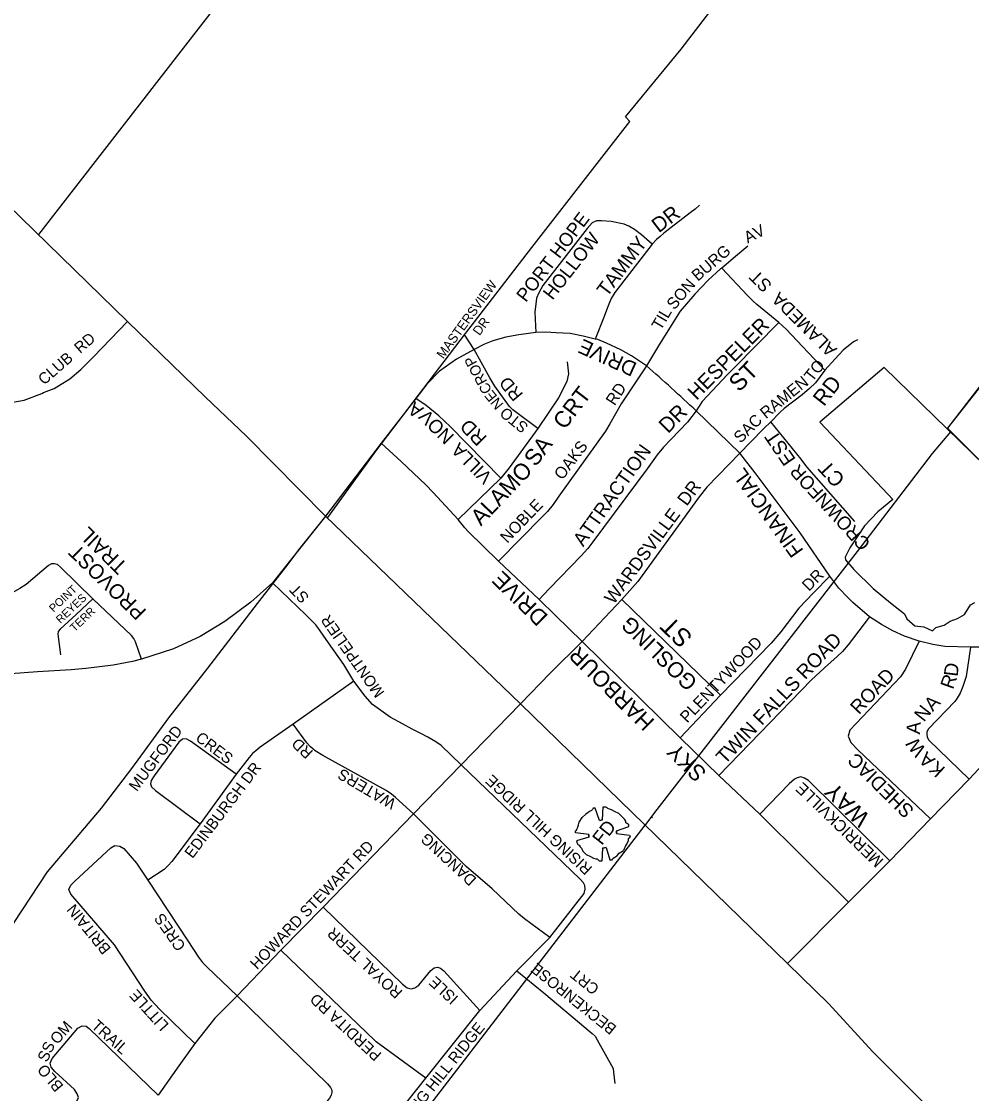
# Model space of a CAD drawing. Extents: x 586326 to 623965, y 4819854 to 4857850.
# Drawn here: x 597455 to 598761, y 4831288 to 4832762 of the extents above; entities that cross this region are included whole.
import ezdxf

# ---------------------------------------------------------------- set-up
doc = ezdxf.new("R2010")
doc.units = 0
for name, color, linetype in [('Fire Syms', 7, 'Continuous'), ('Lots_Concessions', 7, 'Continuous'), ('Major Rds and Hwys', 7, 'Continuous'), ('Minor Rd Lbls', 7, 'Continuous'), ('Minor Rds', 7, 'Continuous'), ('Park Outlines', 7, 'Continuous'), ('Proposed Minor Rds', 7, 'Continuous'), ('Proposed Rd Lbls', 7, 'Continuous'), ('Proposed Secondary Rds', 7, 'Continuous'), ('Secondary Rds Lbls', 7, 'Continuous')]:
    doc.layers.add(name, color=color, linetype=linetype)

msp = doc.modelspace()

# ---------------------------------------------------------------- linework, layer by layer
at = {"layer": 'Fire Syms'}
for points in [[(598254, 4831664.4), (598250, 4831663.4), (598244, 4831680.4), (598241, 4831680.4), (598240, 4831678.4), (598239, 4831677.4), (598237, 4831676.4), (598234, 4831674.4), (598231, 4831672.4), (598226, 4831667.4), (598226, 4831667.4)], [(598250, 4831663.4), (598254, 4831664.4), (598255, 4831682.4), (598258, 4831682.4), (598260, 4831681.4), (598261, 4831680.4), (598263, 4831679.4), (598266, 4831678.4), (598270, 4831676.4), (598276, 4831673.4), (598276, 4831673.4)], [(598273, 4831645.4), (598273, 4831649.4), (598290, 4831655.4), (598290, 4831657.4), (598288, 4831659.4), (598286, 4831660.4), (598286, 4831662.4), (598284, 4831665.4), (598281, 4831668.4), (598276, 4831673.4), (598276, 4831673.4)], [(598235, 4831640.4), (598235, 4831644.4), (598217, 4831646.4), (598217, 4831649.4), (598218, 4831650.4), (598219, 4831652.4), (598220, 4831654.4), (598221, 4831657.4), (598222, 4831661.4), (598226, 4831667.4), (598226, 4831667.4)], [(598235, 4831644.4), (598235, 4831640.4), (598218, 4831635.4), (598219, 4831632.4), (598220, 4831630.4), (598222, 4831629.4), (598223, 4831627.4), (598225, 4831625.4), (598227, 4831621.4), (598232, 4831616.4), (598232, 4831616.4)], [(598273, 4831649.4), (598273, 4831645.4), (598291, 4831643.4), (598292, 4831641.4), (598290, 4831639.4), (598289, 4831638.4), (598289, 4831635.4), (598288, 4831632.4), (598286, 4831629.4), (598283, 4831622.4), (598283, 4831622.4)], [(598259, 4831626.4), (598254, 4831625.4), (598253, 4831607.4), (598250, 4831607.4), (598249, 4831608.4), (598247, 4831610.4), (598245, 4831610.4), (598242, 4831611.4), (598238, 4831613.4), (598232, 4831616.4), (598232, 4831616.4)], [(598254, 4831625.4), (598259, 4831626.4), (598264, 4831609.4), (598267, 4831609.4), (598268, 4831611.4), (598270, 4831612.4), (598272, 4831613.4), (598274, 4831615.4), (598277, 4831618.4), (598283, 4831622.4), (598283, 4831622.4)]]:
    msp.add_lwpolyline(points, dxfattribs=at)
at = {"layer": 'Lots_Concessions'}
for p, q in [((597478.9, 4832469.2), (597897.6, 4833009.7)), ((598362.1, 4832724.3), (598444.3, 4832831.5)), ((598285.4, 4832631.1), (598362.1, 4832724.3)), ((598291.5, 4832625), (598285.4, 4832631.1)), ((598156.6, 4832451.5), (598291.5, 4832625)), ((598065.7, 4832333.1), (598156.6, 4832451.5)), ((597943.4, 4832173.1), (598065.7, 4832333.1)), ((598728.5, 4832202.6), (598825, 4832325.7)), ((598733.1, 4832198.2), (598728.5, 4832202.6)), ((598707.8, 4832168), (598733.1, 4832198.2)), ((597876, 4832080.2), (597943.4, 4832173.1)), ((598604.6, 4832033.6), (598707.8, 4832168)), ((597836.3, 4832035.9), (597873.8, 4832082.4)), ((597821.7, 4832016.2), (597836.3, 4832035.9)), ((598326.1, 4831674.5), (598604.6, 4832033.6)), ((597779.4, 4831961.7), (597821.7, 4832016.2)), ((597711.1, 4831873.2), (597779.4, 4831961.7)), ((597657.4, 4831804.5), (597711.1, 4831873.2)), ((597606.5, 4831734.9), (597657.4, 4831804.5)), ((597564.9, 4831680.5), (597606.5, 4831734.9)), ((597490.6, 4831592.9), (597564.9, 4831680.5)), ((598312.7, 4831656.4), (598326.1, 4831674.5)), ((597983.3, 4831228.8), (598312.5, 4831657)), ((598322.7, 4831667.2), (598321.5, 4831668.3)), ((597455.3, 4831539.2), (597490.6, 4831592.9)), ((597390.4, 4831441.5), (597455.3, 4831539.2))]:
    msp.add_line(p, q, dxfattribs=at)
at = {"layer": 'Major Rds and Hwys'}
for points in [[(597600.8, 4832349.8), (597416.6, 4832528.7)], [(597764.1, 4832192.2), (597708, 4832245.9), (597600.8, 4832349.8)], [(597873.1, 4832082.2), (597764.1, 4832192.2)], [(598141, 4831823.8), (597873.1, 4832082.2)], [(598295.1, 4831674), (598141, 4831823.8)], [(598310.8, 4831658.8), (598295.1, 4831674)], [(598508.3, 4831466.6), (598310.8, 4831658.8)], [(598750.9, 4831220), (598746.2, 4831224.7), (598688.6, 4831282.5), (598625.3, 4831345.9), (598565.4, 4831411.5), (598508.3, 4831466.6)]]:
    msp.add_lwpolyline(points, dxfattribs=at)
at = {"layer": 'Minor Rds'}
for points in [[(598387.2, 4832509.6), (598381.2, 4832504.3), (598374.7, 4832499.3), (598338.3, 4832471), (598333, 4832466.8), (598328.2, 4832462.5), (598322.1, 4832456.2)], [(598322.1, 4832456.2), (598307.7, 4832468.9), (598297.7, 4832476.4), (598290.3, 4832480.7), (598283.5, 4832483.6), (598265.6, 4832487.1), (598252.5, 4832488.3), (598245.7, 4832488), (598239.6, 4832485.6), (598233, 4832477.5), (598171.9, 4832399.3), (598166.4, 4832389.2), (598163.3, 4832381.8), (598162.1, 4832373.4)], [(598322.1, 4832456.2), (598270.9, 4832389.7), (598266, 4832381.4), (598262.5, 4832373.5)], [(598453.6, 4832453.5), (598436.6, 4832439.2), (598417.8, 4832423.1)], [(598417.8, 4832423.1), (598416.3, 4832422), (598399.4, 4832406.8), (598381, 4832387.5), (598360.7, 4832363.9), (598341.3, 4832333.1)], [(598496.5, 4832348.3), (598466.2, 4832372.9), (598460.5, 4832378.1), (598453.2, 4832385.6), (598417.8, 4832423.1)], [(598162.1, 4832373.4), (598161, 4832363.2), (598161.3, 4832352.8), (598162.4, 4832334.6)], [(598262.5, 4832373.5), (598259.6, 4832365.4), (598256.3, 4832356.5), (598244, 4832325.3)], [(597485, 4832251.9), (597499.7, 4832257.5), (597521.2, 4832270.8), (597536.5, 4832283.8), (597554, 4832301.1), (597600.8, 4832349.8)], [(598496.5, 4832348.3), (598434.4, 4832285.6), (598425.7, 4832276.8)], [(598559.7, 4832282.6), (598506.5, 4832339), (598496.5, 4832348.3)], [(598077.4, 4832311.2), (598064.6, 4832331)], [(598341.3, 4832333.1), (598330.8, 4832316.4), (598314.5, 4832288.8)], [(598604.5, 4832324.4), (598599.3, 4832321.6), (598585.1, 4832310.2), (598573.9, 4832298.2), (598559.7, 4832282.6)], [(598098.8, 4832272.2), (598087.2, 4832293.8), (598077.4, 4832311.2)], [(598205.2, 4832294.5), (598207, 4832277.6), (598204.7, 4832267.2), (598193.6, 4832244.6), (598164.9, 4832202.7)], [(598314.5, 4832288.8), (598285.1, 4832244.9)], [(598425.7, 4832276.8), (598391.2, 4832239.8), (598382.7, 4832227.1)], [(598559.7, 4832282.6), (598546.7, 4832265.3), (598538.4, 4832257.8), (598528.3, 4832249.1), (598503.6, 4832229.9), (598497.8, 4832224.7), (598485.3, 4832211.8)], [(598164.9, 4832202.7), (598137.7, 4832222.7), (598130.8, 4832228.3), (598126.1, 4832232.7), (598106, 4832260.7), (598098.8, 4832272.2)], [(597342.4, 4832228.8), (597408.2, 4832234.8), (597432.4, 4832237.1), (597458.7, 4832241.6), (597482.8, 4832250.6), (597485, 4832251.9)], [(598028.7, 4832220.2), (598011.5, 4832234.3), (597997.2, 4832243.9)], [(598285.1, 4832244.9), (598279.6, 4832236.3), (598264.2, 4832209), (598258.2, 4832198.8), (598193.7, 4832109.6), (598186.1, 4832098.3), (598178.1, 4832088.6), (598171.3, 4832081.7), (598110.8, 4832020)], [(598113.9, 4832134.5), (598044.5, 4832205.2), (598028.7, 4832220.2)], [(598382.7, 4832227.1), (598370.9, 4832211.4), (598348.2, 4832187.8)], [(598164.9, 4832202.7), (598125.6, 4832148.4), (598113.9, 4832134.5)], [(598475.8, 4832202.7), (598457.3, 4832183.6), (598442.6, 4832168.6)], [(598485.3, 4832211.8), (598475.8, 4832202.7)], [(598600.9, 4832074.6), (598534.9, 4832150), (598527, 4832160.3), (598485.3, 4832211.8)], [(598348.2, 4832187.8), (598337.8, 4832177), (598329.2, 4832166.4), (598315.2, 4832147), (598240.6, 4832046.6), (598233.9, 4832037.6), (598224.5, 4832027.5), (598181.1, 4831982.6), (598172.7, 4831973.7), (598166.8, 4831967.3)], [(597977, 4832157), (597949.6, 4832182.5)], [(598055.4, 4832077.4), (598021.2, 4832114.7), (598010.8, 4832125.2), (597977, 4832157)], [(598113.9, 4832134.5), (598055.4, 4832077.4)], [(598110.8, 4832020), (598069.3, 4832061.1), (598064.8, 4832066.1), (598055.4, 4832077.4)], [(597553.1, 4831968.3), (597508.6, 4832011.9), (597504.5, 4832015.5), (597500, 4832016.7), (597496.3, 4832016.3), (597491.9, 4832014.2), (597461.2, 4831988), (597452.7, 4831982.4), (597401.9, 4831953.9)], [(598166.8, 4831967.3), (598110.8, 4832020)], [(598566.6, 4831999.4), (598543.9, 4831976.5), (598523.8, 4831955.3), (598499, 4831922.8), (598485.9, 4831907.4), (598416, 4831835.9)], [(597911.7, 4831855.2), (597898, 4831877.8), (597877.1, 4831907.6), (597862.2, 4831929), (597859.8, 4831932.6), (597846, 4831946.5), (597800.2, 4831990.4)], [(597553.1, 4831968.3), (597530.1, 4831946.8), (597508.2, 4831926.5), (597505.5, 4831923.5), (597504.9, 4831919.8), (597508.4, 4831891.3)], [(597619.9, 4831885.5), (597611.7, 4831909.2), (597609.5, 4831913.6), (597606.1, 4831917.7), (597553.1, 4831968.3)], [(598189.3, 4831945.5), (598166.8, 4831967.3)], [(598280.6, 4831967.2), (598416, 4831835.9)], [(598226, 4831909.8), (598189.3, 4831945.5)], [(598621.2, 4831943.8), (598592, 4831905.2), (598584, 4831895.8), (598576.8, 4831889.2), (598559.4, 4831873.6), (598541, 4831856.5), (598413.9, 4831725.5)], [(598360.9, 4831777.2), (598226, 4831909.8)], [(598689.3, 4831909.9), (598670.8, 4831871.5), (598663.7, 4831861), (598594, 4831787.9), (598591.8, 4831779.3), (598595.4, 4831770.7), (598605, 4831760.9), (598705.2, 4831665.9)], [(598759.9, 4831901.7), (598754, 4831861.7), (598749.7, 4831847.9), (598745.7, 4831838.8), (598741.6, 4831831.9), (598738.4, 4831827.2), (598702.1, 4831789.7), (598700.1, 4831785.5), (598699.8, 4831782), (598700.5, 4831778.2), (598702.6, 4831774.1), (598758, 4831720.3)], [(597911.7, 4831855.2), (597828.7, 4831795.9)], [(598059.3, 4831740), (598032, 4831766.5), (598024.8, 4831771.9), (598013.9, 4831778.2), (598003.9, 4831783.3), (597992, 4831789.1), (597978.9, 4831796.2), (597961.8, 4831805.6), (597937.8, 4831823), (597927.7, 4831834.3), (597911.7, 4831855.2)], [(598416, 4831835.9), (598360.9, 4831777.2)], [(598141, 4831823.8), (598059.3, 4831740)], [(597828.7, 4831795.9), (597783.1, 4831764.2), (597777, 4831759.5), (597772.6, 4831755.5), (597767.9, 4831750.3), (597750.2, 4831727.2)], [(597994.1, 4831672.5), (597969.1, 4831695.3), (597963.5, 4831699.9), (597956.2, 4831704.6), (597869.1, 4831752.8), (597858.9, 4831759.1), (597852.5, 4831764.7), (597847.3, 4831770.4), (597828.7, 4831795.9)], [(597750.2, 4831727.2), (597687.4, 4831772.7), (597681.5, 4831776), (597676.3, 4831775.4), (597671.2, 4831771.2), (597637.1, 4831724.9), (597633.2, 4831718.5), (597632.1, 4831713.8), (597633.8, 4831709.7), (597639.3, 4831704.6), (597700.7, 4831658.7)], [(598413.9, 4831725.5), (598360.9, 4831777.2)], [(598059.3, 4831740), (597994.1, 4831672.5)], [(598181.4, 4831502.7), (598228.5, 4831563.2), (598230, 4831569.2), (598229.8, 4831574.1), (598227.6, 4831577.9), (598223.2, 4831582.8), (598059.3, 4831740)], [(597750.2, 4831727.2), (597700.7, 4831658.7)], [(598470.1, 4831672.1), (598413.9, 4831725.5)], [(598648.9, 4831608.2), (598537.3, 4831718.4), (598531.7, 4831721.7), (598526.7, 4831723.4), (598521.6, 4831722.2), (598517.8, 4831720.3), (598510.8, 4831713.9), (598470.1, 4831672.1)], [(597994.1, 4831672.5), (597869.8, 4831544.4)], [(598181.4, 4831502.7), (598146.7, 4831528.1), (598139, 4831534.5), (598102.3, 4831569.7), (598066.6, 4831600.4), (597994.1, 4831672.5)], [(598592.4, 4831551.1), (598470.1, 4831672.1)], [(597700.7, 4831658.7), (597661.6, 4831607.1), (597656.6, 4831601.7), (597650.9, 4831596.3), (597628.7, 4831581.5)], [(597693.4, 4831356.9), (597644.6, 4831404.2), (597633.3, 4831416.2), (597624.6, 4831428.9), (597582.9, 4831492.4), (597522.6, 4831562.3), (597520.1, 4831568.6), (597522.5, 4831574.6), (597528.2, 4831579.9), (597577.6, 4831626.1), (597583.2, 4831628.9), (597590, 4831628.4), (597595.8, 4831624.8), (597612.8, 4831604.8), (597628.7, 4831581.5)], [(597628.7, 4831581.5), (597683.6, 4831497.9), (597698.3, 4831475.5), (597703.8, 4831468.3), (597710.1, 4831461.6), (597751.3, 4831422.5)], [(597869.8, 4831544.4), (597811.3, 4831485)], [(597869.8, 4831544.4), (597978.9, 4831438.3), (597985.2, 4831433.3), (597990.6, 4831432.2), (597995.9, 4831433.4), (598001.1, 4831436.9), (598017.6, 4831457.3), (598022.3, 4831460.8), (598026.9, 4831461.8), (598031.3, 4831460.5), (598035.5, 4831456.8), (598085, 4831402.1)], [(598136.3, 4831456.9), (598181.4, 4831502.7)], [(597811.3, 4831485), (597751.3, 4831422.5)], [(598010.8, 4831308.9), (597942.5, 4831359.2), (597941.1, 4831360.5), (597811.3, 4831485)], [(598085, 4831402.1), (598136.3, 4831456.9)], [(597751.3, 4831422.5), (597720.7, 4831391.7), (597693.4, 4831356.9)], [(597751.3, 4831422.5), (597875.7, 4831301.3), (597879.9, 4831296.1), (597881.5, 4831292.6), (597881.5, 4831289.2), (597880.6, 4831285.6), (597878.5, 4831281.5), (597842.7, 4831237.1), (597838.8, 4831230.8), (597837.1, 4831225.7), (597838.3, 4831220.4), (597840.9, 4831216.1), (597884.1, 4831176.3), (597890.3, 4831172.2), (597896.4, 4831171), (597902, 4831173.4), (597906.8, 4831178), (598010.8, 4831308.9)], [(598010.8, 4831308.9), (598085, 4831402.1)], [(597693.4, 4831356.9), (597669.1, 4831322.9), (597668, 4831321.4)]]:
    msp.add_lwpolyline(points, dxfattribs=at)
at = {"layer": 'Park Outlines'}
msp.add_lwpolyline([(598866.1, 4832067.7), (598641.3, 4832286.6), (598552.7, 4832211.2), (598646.6, 4832111.6), (598653, 4832104.8), (598632.8, 4832088.1), (598614.1, 4832068.8), (598594, 4832038.4), (598587.6, 4832025.6), (598588.3, 4832021.9), (598599.5, 4832008.7), (598626.1, 4831982.6), (598649.8, 4831962.8), (598669.2, 4831947.9), (598672.4, 4831940.8), (598683.4, 4831931.2), (598695.7, 4831929.8), (598707.8, 4831924.4), (598712.5, 4831928.8), (598723.7, 4831932), (598732.1, 4831937.4), (598742, 4831941.2), (598751.7, 4831946.8), (598760.2, 4831960.2), (598766, 4831963.2)], dxfattribs=at)
msp.add_lwpolyline([(598781.6, 4832272.1), (598780.5, 4832270.7), (598728.4, 4832203), (598733.1, 4832198.3), (598791, 4832140.4), (598806.3, 4832155.7), (598836.3, 4832177.6), (598836.7, 4832180.6), (598837.7, 4832183.4), (598839.2, 4832186.1), (598841.1, 4832188.4), (598843.4, 4832190.3), (598846.1, 4832191.7), (598848.9, 4832192.6), (598851.9, 4832193), (598854.9, 4832192.8), (598857.8, 4832192), (598860.6, 4832190.7), (598863, 4832188.9), (598849.8, 4832202.3), (598846.3, 4832205.9), (598781.6, 4832272.1)], close=True, dxfattribs=at)
at = {"layer": 'Proposed Minor Rds'}
for points in [[(598136.3, 4831456.9), (598173, 4831426.3)], [(598173, 4831426.3), (598239.6, 4831370.7), (598243.8, 4831366.7), (598246.6, 4831362), (598268.6, 4831322.3), (598269.2, 4831317.4)], [(597447.7, 4831182.5), (597506.3, 4831246), (597529.3, 4831273.7), (597533.3, 4831282.4), (597531.5, 4831287.7), (597527.6, 4831293.6), (597500.5, 4831318.5), (597495.7, 4831324.4), (597494.2, 4831329.9), (597497.2, 4831336.1), (597532.1, 4831378.1), (597538.2, 4831381.3), (597543.7, 4831380.8), (597548.1, 4831377.5), (597642.7, 4831285.9)], [(597668, 4831321.4), (597642.7, 4831285.9)], [(598269.2, 4831317.4), (598270.9, 4831301.6)]]:
    msp.add_lwpolyline(points, dxfattribs=at)
at = {"layer": 'Proposed Secondary Rds'}
for points in [[(598162.4, 4832334.6), (598139, 4832331.6), (598120.8, 4832328.3), (598103.1, 4832323), (598091.7, 4832318.5), (598077.4, 4832311.2)], [(598244, 4832325.3), (598227.5, 4832329.5), (598209.4, 4832333.2), (598190.3, 4832334.3), (598175.7, 4832335.2), (598162.4, 4832334.6)], [(598314.5, 4832288.8), (598293.9, 4832302.4), (598278.9, 4832310.9), (598259.5, 4832320.1), (598247.5, 4832324.9), (598244, 4832325.3)], [(598077.4, 4832311.2), (598052.9, 4832298), (598029.6, 4832281.4), (598012.2, 4832263.4), (597997.2, 4832243.9)], [(597997.2, 4832243.9), (597949.6, 4832182.5)], [(598442.6, 4832168.6), (598382.7, 4832227.1)], [(597949.6, 4832182.5), (597873.1, 4832082.2)], [(598442.6, 4832168.6), (598397.6, 4832122), (598387, 4832108.4), (598318.3, 4832013.5), (598302.5, 4831992.4), (598280.6, 4831967.2)], [(598566.6, 4831999.4), (598525.8, 4832059.1), (598463.8, 4832141.4), (598442.6, 4832168.6)], [(597873.1, 4832082.2), (597800.2, 4831990.4)], [(598621.2, 4831943.8), (598598.1, 4831963.5), (598591.1, 4831970.1), (598579.1, 4831983.1), (598566.6, 4831999.4)], [(597800.2, 4831990.4), (597770.3, 4831963.8), (597734.7, 4831937.2), (597700.7, 4831916.4), (597663.9, 4831899.8), (597619.9, 4831885.5)], [(598280.6, 4831967.2), (598226, 4831909.8)], [(598689.3, 4831909.9), (598669.3, 4831917.1), (598653.1, 4831924.3), (598637.5, 4831933), (598621.2, 4831943.8)], [(598226, 4831909.8), (598181.8, 4831866.1), (598141, 4831823.8)], [(598759.9, 4831901.7), (598724.8, 4831903), (598708.4, 4831905.5), (598689.3, 4831909.9)], [(598840.9, 4831900.4), (598839.7, 4831861.5), (598836, 4831840.2), (598830.9, 4831822), (598824.8, 4831806.4), (598816.6, 4831790.6), (598806, 4831774), (598797.1, 4831762), (598758, 4831720.3)], [(598840.9, 4831900.4), (598785.1, 4831901.7), (598759.9, 4831901.7)], [(597619.9, 4831885.5), (597607.3, 4831882.1), (597581.1, 4831877), (597543.5, 4831872.5)], [(597543.5, 4831872.5), (597523.1, 4831870.8), (597476.7, 4831868.1), (597440.1, 4831865.4), (597417.2, 4831862.6), (597381.7, 4831854.2), (597350.7, 4831844.7), (597300.5, 4831821.9)], [(598758, 4831720.3), (598705.2, 4831665.9)], [(598705.2, 4831665.9), (598648.9, 4831608.2)], [(598648.9, 4831608.2), (598592.4, 4831551.1)], [(598592.4, 4831551.1), (598508.3, 4831466.6)]]:
    msp.add_lwpolyline(points, dxfattribs=at)
msp.add_arc((595938.4, 4829591.4), 3594.6, 47.1577, 48.6239, dxfattribs=at)

# ---------------------------------------------------------------- texts
at = {"layer": 'Fire Syms'}
msp.add_text('FD', height=18.74, rotation=51.6654, dxfattribs=at).set_placement((598253, 4831628.4))
at = {"layer": 'Minor Rd Lbls'}
for s, height, rotation, p in [('PORT HOPE', 18.51, 52.5796, (598148.6, 4832375.1)), ('DR', 20.41, 37.1111, (598331.3, 4832470.9)), ('AV', 15.99, 27.0275, (598453.6, 4832456.9)), ('HOLLOW', 18.51, 51.9344, (598185.1, 4832378.2)), ('TAMMY', 19.44, 53.0873, (598260.1, 4832382.4)), ('BURG', 15.99, 40.7655, (598385, 4832404.3)), ('MASTERSVIEW', 12.852, 54.0501, (598035, 4832297.4)), ('SON', 15.99, 49.502, (598352.7, 4832364.8)), ('ALAMEDA  ST', 17.63, 135.2385, (598577.5, 4832312.1)), ('TIL', 15.99, 59.4593, (598334.1, 4832336.5)), ('DR', 12.85, 54.0501, (598084.8, 4832329.5)), ('HESPELER', 20.26, 45.1603, (598383.1, 4832240.5)), ('CLUB  RD', 15.3, 41.0752, (597485.9, 4832261.6)), ('CROP', 14.43, 118.4897, (598102.4, 4832255)), ('ST', 23.48, 45.1603, (598441.8, 4832251.7)), ('TO', 15.99, 51.9065, (598542.4, 4832265.9)), ('RAMEN', 15.99, 39.0629, (598478.7, 4832215.1)), ('RD', 17.63, 129.945, (598145.7, 4832249.7)), ('CRT', 22.5, 52.6626, (598201.9, 4832199.8)), ('RD', 15.99, 56.6684, (598270.6, 4832233)), ('RD', 21.49, 51.9065, (598558.4, 4832231.9)), ('NE', 14.43, 129.1848, (598118.7, 4832236)), ('A', 18.9, 143.6349, (598009.1, 4832230.5)), ('DR', 20.86, 45.1603, (598343.9, 4832194.9)), ('NOV', 18.67, 135.2652, (598051, 4832192.5)), ('STO', 15.19, 141.0836, (598153.2, 4832206.8)), ('SAC', 15.99, 45.1603, (598443.9, 4832181.5)), ('RD', 19.44, 134.5348, (598096.2, 4832190.5)), ('SA', 22.5, 52.6626, (598162, 4832148.9)), ('EST', 19.44, 124.3273, (598520.4, 4832160.1)), ('VILLA', 18.12, 134.3846, (598103.5, 4832137.2)), ('OAKS', 15.99, 52.7899, (598198.7, 4832130.8)), ('ATTRACTION ', 19.094, 54.6172, (598227.4, 4832039)), ('ALAMO', 22.5, 46.5436, (598086.7, 4832067.5)), ('CROWNFOR', 18.51, 132.3941, (598623.8, 4832045.2)), ('CT', 20.41, 132.3941, (598588.6, 4832133.4)), ('WARDSVILLE  DR', 17.998, 53.4095, (598269.3, 4831959.6)), ('NOBLE', 15.99, 46.1669, (598123, 4832043.9)), ('TRAIL', 20.36, 135.658, (597602, 4832015)), ('PROVOST', 20.36, 135.658, (597627.7, 4831951.9)), ('SKY     HARBOUR       DRIVE', 22.135, 135.4748, (598398.4, 4831730.3)), ('DR', 15.99, 45.1603, (598537.9, 4831977.9)), ('POINT', 11.15, 43.2861, (597499.1, 4831949)), ('ST', 15.3, 133.5143, (597851.5, 4831971.1)), ('REYES', 11.15, 43.2861, (597508.5, 4831933.7)), ('TERR', 11.15, 43.2861, (597527.8, 4831922.2)), ('MONTPELIER', 15.3, 125.2776, (597954.8, 4831839.4)), ('GOSLING', 21.43, 135.7588, (598385.9, 4831855.2)), ('ST', 24.81, 135.7588, (598379.3, 4831916.6)), ('PLENTYWOOD', 15.99, 46.5701, (598370.4, 4831796.7)), ('TWIN FALLS ROAD', 19.465, 46.5701, (598422.4, 4831739.6)), ('D', 19.1, 83.1593, (598742.2, 4831860.8)), ('ROAD', 19.09, 46.5701, (598606.5, 4831808.2)), ('R', 19.1, 70.435, (598735.9, 4831842.9)), ('A', 19.1, 47.0303, (598708.2, 4831812.4)), ('N', 19.1, 52, (598696, 4831798)), ('MUGFORD', 15.3, 52.8397, (597613.4, 4831702.5)), ('A', 19.1, 85.6901, (598690.5, 4831781.6)), ('CRES', 15.3, 322.8397, (597693, 4831774.5)), ('RD', 15.3, 137.0893, (597856.9, 4831758.2)), ('W', 19.1, 127.9638, (598699.9, 4831760.7)), ('A', 19.1, 137.4503, (598712.7, 4831747.9)), ('SHEDIAC ', 19.09, 135.4748, (598683.7, 4831678.5)), ('K', 19.1, 137.4503, (598726.6, 4831735.1)), ('EDINBURGH DR', 15.299, 52.8397, (597690, 4831610.3)), ('WATERS', 15.3, 149.5472, (597971.3, 4831691.2)), ('RISING HILL RIDGE', 15.299, 137.0893, (598241, 4831598.5)), ('MERRICKVILLE', 15.911, 136.0814, (598641.6, 4831609)), ('WAY', 22.8, 135.4748, (598623, 4831668.8)), ('DANCING', 15.3, 137.0893, (598081.7, 4831583.4)), ('HOWARD STEWART RD', 15.299, 46.352, (597778.9, 4831457.5)), ('BRITAIN', 15.3, 129.0416, (597578.7, 4831487.3)), ('CRES', 15.3, 124.8947, (597681.4, 4831490.8)), ('ROYAL TERR', 15.3, 137.0893, (597980, 4831428.5)), ('ISLE', 15.3, 137.0893, (598056.7, 4831420.3)), ('LITTLE', 15.3, 132.0949, (597658.4, 4831382.7)), ('PERDITA RD', 15.3, 137.0893, (597951.2, 4831342.6)), ('RISING HILL RIDGE', 15.299, 51.026, (597973.5, 4831230.4))]:
    msp.add_text(s, height=height, rotation=rotation, dxfattribs=at).set_placement(p)
at = {"layer": 'Proposed Rd Lbls'}
for s, rotation, p in [('BECKENROSE', 141.3089, (598274.4, 4831379.8)), ('CRT', 141.3089, (598250.7, 4831434.5)), ('TRAIL', 318.3035, (597549.9, 4831379.4)), ('OM', 48.3035, (597504.1, 4831354.6)), ('SS', 65.2548, (597490, 4831330.1)), ('BLO', 129.8922, (597513.4, 4831298.5))]:
    msp.add_text(s, height=15.3, rotation=rotation, dxfattribs=at).set_placement(p)
at = {"layer": 'Secondary Rds Lbls'}
for s, rotation, p in [('DRIVE', 155.593, (598302.7, 4832292)), ('FINANCIAL ', 125.6404, (598531.1, 4832034.7))]:
    msp.add_text(s, height=20.36, rotation=rotation, dxfattribs=at).set_placement(p)

doc.saveas('drawing.dxf')
